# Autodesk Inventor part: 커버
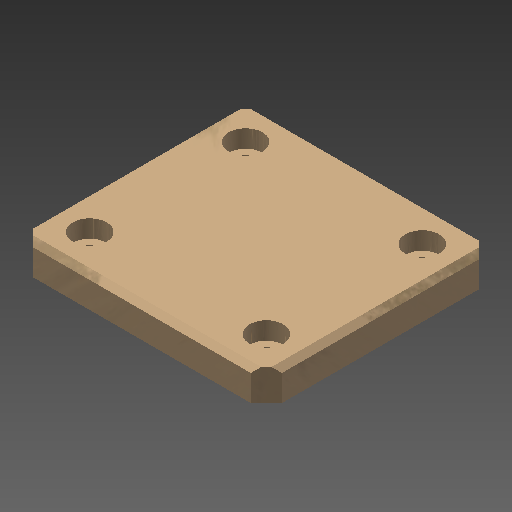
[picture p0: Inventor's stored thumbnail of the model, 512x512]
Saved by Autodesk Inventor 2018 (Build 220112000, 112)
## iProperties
Created: 2023-03
Part Number: 커버
Material: 알루미늄 6061
Document SubType Name: Modeling
Designer: mdu-01
Density: 1 g/cm^3
Appearance: 알루미늄 - 평지(3)
Author: mdu-01
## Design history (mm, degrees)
sketch "스케치1"
  geometry: L1 (-24, -22)-(24, -22); L2 (24, -22)-(24, 22); L3 (24, 22)-(-24, 22); L4 (-24, 22)-(-24, -22); L5 (-24, -22)-(24, 22); L6 (24, -22)-(-24, 22); 2 further points
  constraints: 12 end point, 2 midpoint, 2 parallel, 1 horizontal, 1 perpendicular, 1 point on line, 1 other
  dimensions: "d2" = 1 distance from line of L4 point (-25, -22)
extrude "돌출1" new body sketch "스케치1" distance "d0" = 6; taper "d1" = 0 deg
hole "구멍1" diameter "d6" = 3.4; stored, may be unused: countersink angle "d10" = 90 deg, drill point angle "d12" = 118 deg; dims "d4" = 7, "d5" = 7, "d7" = 6, "d8" = 6.5, "d9" = 3.4, "d11" = 8
chamfer "모따기1" distance "d13" = 3; stored, may be unused: second distance "d14" = 2, angle "d15" = 45 deg
chamfer "모따기2" distance "d16" = 1; stored, may be unused: second distance "d17" = 2, angle "d18" = 45 deg
node "솔리드1"
mirror "대칭1"
mirror "대칭2"
